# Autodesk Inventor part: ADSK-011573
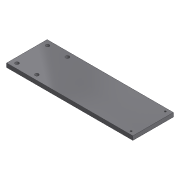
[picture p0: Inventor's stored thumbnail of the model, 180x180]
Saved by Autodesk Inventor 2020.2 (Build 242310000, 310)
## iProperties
Created: 2000-02
Part Number: ADSK-011573
Document SubType Name: Modeling
Designer: sspink
Material: Acier doux
Density: 7.86 g/cm^3
Appearance: Metal-Steel(Polish)
Mass: 2527.36 g
Surface Area: 741.001 cm^2
Volume: 321.547 cm^3
Control State: 0
Checked Out: False
Master: False
Shininess: 60.0
Length Units: 11269
Angle Units: 11279
Time Units: 11290
Mass Units: 11283
Length Display Precision: 3
Angle Display Precision: 2
Compacted: True
Cutlength: 12.5
Material Description: FLAT,HRS,0.375X04.000
Material_Number: A084411
Dimensions: 10x102x318 mm
Mass: 2,527 kg
VLT_Material: Acier doux
Density: 7.859999999999999
Volumn: 196.64476800000017
Area: 470.96680000000003
PropertySet Name: Model Information
Author: sspink
Revision Number: -
Title: ADSK-011573
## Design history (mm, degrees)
node "Extrusion1" dims "d2" = 102, "d3" = 0
  sketch "Sketch1"
    geometry: L1 (0, 0)-(318, 0); L2 (318, 0)-(318, 10); L3 (318, 10)-(0, 10); L4 (0, 10)-(0, 0)
    constraints: 8 end point, 2 parallel, 1 horizontal, 1 perpendicular
    dimensions: "d0" = 318 distance of L1.start L1.end; "d1" = 10 distance between parallel lines of L1 L3
node "Hole1" dims "d8" = 9, "d9" = 9.525, "d10" = 6.35, "d11" = 60 deg, "d12" = 19.05, "d13" = 118 deg, "d26" = 6
  sketch "Sketch2"
    geometry: L1 (0, 0)-(0, -102) reference; L2 (13.5, -12.5)-(63.5, -12.5); L3 (63.5, -12.5)-(63.5, -89.5); L4 (63.5, -89.5)-(13.5, -89.5); L5 (13.5, -89.5)-(13.5, -12.5); 4 further points
    constraints: 8 end point, 3 horizontal alignment, 2 midpoint, 2 parallel, 2 vertical alignment, 1 horizontal, 1 perpendicular
    dimensions: "d23" = 77 distance of L2.end L3.end; "d24" = 50 distance of L2.start L2.end; "d25" = 13.5 distance between parallel lines of L1 L5
node "Hole2" dims "d17" = 4.134, "d18" = 9.525, "d19" = 6.35, "d20" = 60 deg, "d21" = 14.2, "d22" = 118 deg, "d27" = 10
  sketch "Sketch3"
    geometry: L1 (318, 0)-(318, -102) reference; L2 (305.5, -94)-(305.5, -8); 2 further points
    constraints: 2 end point, 2 midpoint, 1 horizontal alignment, 1 vertical, 1 vertical alignment
    dimensions: "d28" = 12.5 distance between parallel lines of L1 L2; "d29" = 86 distance of L2.start L2.end
node "Solide1"
node "Corps solides"
node "Corps surfaciques"
